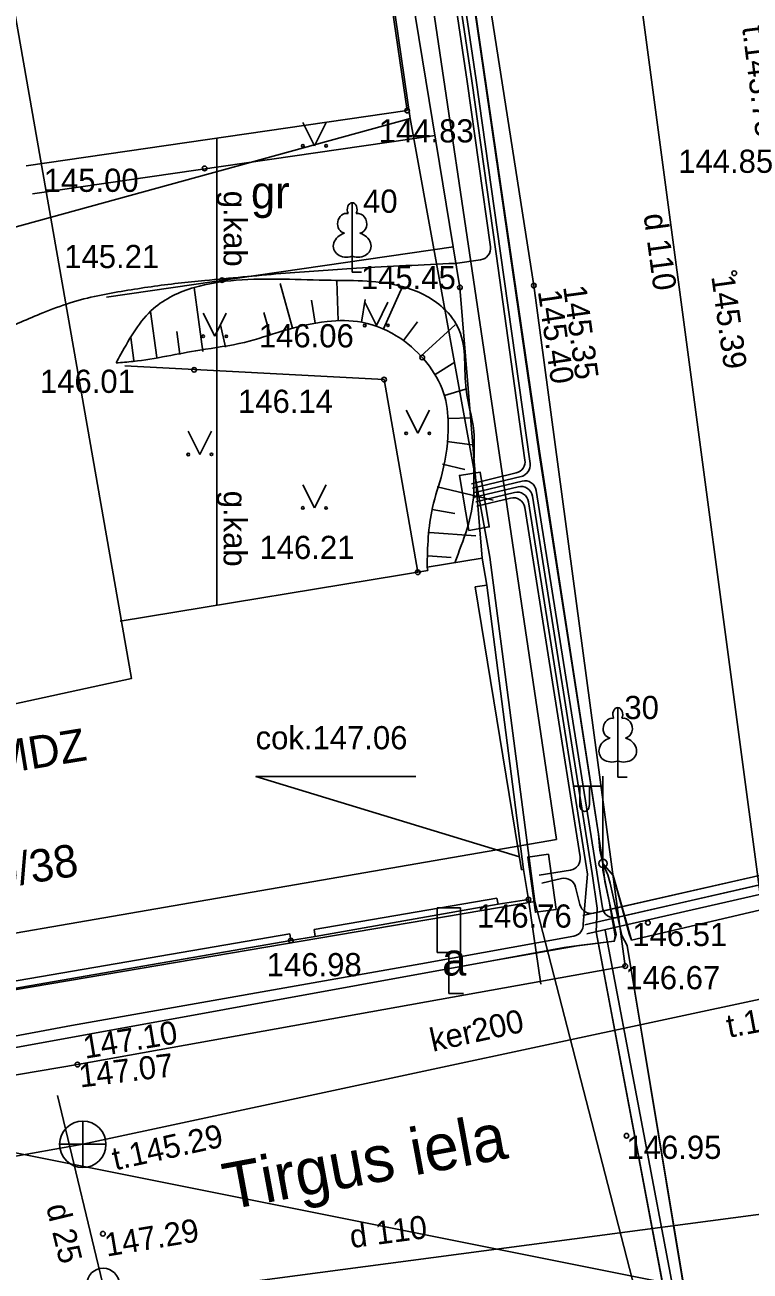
# Model space of a CAD drawing. Extents: x 728710 to 728960, y 272811 to 273475.
# Drawn here: x 728821.98 to 728837.6, y 272956.75 to 272983.61 of the extents above; entities that cross this region are included whole.
import ezdxf

# ---------------------------------------------------------------- set-up
doc = ezdxf.new("R2010")
doc.units = 0
for name, color, linetype in [('GEOD_ELEM_####_TKST_#', 7, 'Continuous'), ('Level 12', 7, 'Continuous'), ('Level 15', 7, 'Continuous'), ('Level 17', 7, 'Continuous'), ('Level 23', 7, 'Continuous'), ('Level 26', 7, 'Continuous'), ('Level 28', 7, 'Continuous'), ('Level 29', 7, 'Continuous'), ('Level 3', 7, 'Continuous'), ('Level 34', 7, 'Continuous'), ('Level 36', 7, 'Continuous'), ('Level 39', 7, 'Continuous'), ('Level 4', 7, 'Continuous'), ('Level 48', 7, 'Continuous'), ('Level 49', 7, 'Continuous'), ('Level 50', 7, 'Continuous'), ('Level 54', 7, 'Continuous'), ('Level 55', 7, 'Continuous'), ('Level 56', 7, 'Continuous'), ('Level 57', 7, 'Continuous'), ('Level 58', 7, 'Continuous'), ('Level 59', 7, 'Continuous'), ('Level 60', 7, 'Continuous'), ('Level 62', 7, 'Continuous'), ('Level 9', 7, 'Continuous'), ('RAMI_UZMR_####_####_#', 7, 'Continuous'), ('RELJ_ELEM_####_####_#', 7, 'Continuous'), ('RELJ_NOGA_####_####_#', 7, 'Continuous'), ('ROBZ_ELEM_####_####_#', 7, 'Continuous'), ('ROBZ_UZMR_####_####_#', 7, 'Continuous'), ('SAKT_VADV_PKAB_TKST_#', 7, 'Continuous'), ('TERT_ELEM_####_####_#', 7, 'Continuous'), ('TERT_KONT_####_####_#', 7, 'Continuous')]:
    doc.layers.add(name, color=color, linetype=linetype)

msp = doc.modelspace()

# ---------------------------------------------------------------- linework, layer by layer
at = {"layer": 'GEOD_ELEM_####_TKST_#'}
for points in [[(728834.432, 272965.54), (728834.353, 272966.059), (728834.337, 272966.173), (728833.056, 272974.371), (728829.783, 272996.939), (728828.856, 273003.445)], [(728834.651, 272965.281), (728835.049, 272963.886), (728848.214, 272966.974), (728858.246, 272968.805), (728863.75, 272969.856)], [(728811.293, 272959.669), (728811.951, 272959.783), (728832.038, 272963.44), (728833.873, 272963.761), (728834.677, 272963.862), (728834.716, 272964.011), (728834.498, 272965.033), (728834.427, 272965.397), (728834.432, 272965.54)], [(728834.957, 272963.773), (728836.299, 272955.654), (728837.635, 272946.696), (728838.556, 272941.827), (728839.286, 272937.451), (728841.341, 272924.237), (728842.91, 272914.786), (728843.079, 272914.144), (728843.387, 272914.165)]]:
    msp.add_lwpolyline(points, dxfattribs=at)
at = {"layer": 'Level 12'}
for p, q in [((728825.811, 272976.575), (728825.628, 272977.952)), ((728827.746, 272977.073), (728827.481, 272978.037)), ((728828.73, 272977.236), (728828.697, 272978.095)), ((728829.706, 272977.058), (728830.11, 272977.973)), ((728828.234, 272977.182), (728828.15, 272977.675)), ((728829.228, 272977.202), (728829.306, 272977.696)), ((728824.82, 272976.443), (728824.688, 272977.434)), ((728827.266, 272976.934), (728827.123, 272977.414)), ((728826.304, 272976.663), (728826.193, 272977.15)), ((728830.137, 272976.806), (728830.435, 272977.208)), ((728830.509, 272976.474), (728831.247, 272977.148)), ((728824.325, 272976.377), (728824.258, 272976.872)), ((728825.316, 272976.509), (728825.25, 272977.005)), ((728830.814, 272976.078), (728831.238, 272976.343)), ((728831.016, 272975.623), (728831.474, 272975.759)), ((728831.096, 272975.131), (728831.596, 272975.14)), ((728831.067, 272974.632), (728831.612, 272974.563)), ((728830.972, 272974.141), (728831.459, 272974.026)), ((728830.857, 272973.655), (728832.066, 272973.367)), ((728830.752, 272973.166), (728831.244, 272973.078)), ((728830.698, 272972.669), (728831.695, 272972.597)), ((728830.661, 272972.171), (728831.16, 272972.134))]:
    msp.add_line(p, q, dxfattribs=at)
msp.add_spline([(728830.643, 272971.921), (728830.76, 272973.208), (728830.969, 272973.952), (728831.096, 272974.994), (728830.999, 272975.681), (728830.636, 272976.329), (728830.076, 272976.85), (728829.238, 272977.201), (728828.491, 272977.219), (728827.534, 272977.015), (728826.707, 272976.768), (728825.748, 272976.602), (728824.313, 272976.359), (728823.942, 272976.326)], degree=3, dxfattribs=at)
at = {"layer": 'Level 15'}
for points in [[(728831.539, 272972.717), (728831.341, 272973.901), (728831.785, 272973.975), (728831.983, 272972.791)], [(728833.259, 272965.738), (728833.423, 272964.549), (728832.977, 272964.488), (728832.813, 272965.677)]]:
    msp.add_lwpolyline(points, close=True, dxfattribs=at)
at = {"layer": 'Level 17'}
for p, q in [((728822.683, 272960.538), (728823.746, 272956.12)), ((728823.317, 272956.063), (728838.727, 272958.097))]:
    msp.add_line(p, q, dxfattribs=at)
msp.add_lwpolyline([(728832.551, 273004.399), (728838.736, 272957.979), (728838.743, 272957.939)], dxfattribs=at)
at = {"layer": 'Level 23'}
for points in [[(728858.12, 272966.472), (728840.671, 272963.226), (728823.226, 272959.486)], [(728811.406, 272957.38), (728823.226, 272959.486)]]:
    msp.add_lwpolyline(points, dxfattribs=at)
at = {"layer": 'Level 26'}
for p, q in [((728834.432, 272965.54), (728834.432, 272967.423)), ((728834.432, 272967.207), (728833.797, 272967.202)), ((728833.932, 272967.203), (728833.932, 272966.811)), ((728834.142, 272967.205), (728834.142, 272966.811))]:
    msp.add_line(p, q, dxfattribs=at)
msp.add_circle((728834.432, 272965.54), 0.09, dxfattribs=at)
msp.add_ellipse((728834.037, 272966.811), major_axis=(0, 0.151), ratio=0.695971, start_param=1.570796, end_param=4.712389, dxfattribs=at)
at = {"layer": 'Level 28'}
msp.add_lwpolyline([(728824.13, 272976.264), (728829.716, 272975.966), (728830.442, 272971.814)], dxfattribs=at)
at = {"layer": 'Level 29'}
for p, q in [((728823.226, 272958.986), (728823.226, 272959.986)), ((728822.726, 272959.486), (728823.726, 272959.486))]:
    msp.add_line(p, q, dxfattribs=at)
msp.add_circle((728823.226, 272959.486), 0.5, dxfattribs=at)
at = {"layer": 'Level 3'}
for p, q in [((728830.214, 272981.763), (728828.214, 272995.554)), ((728822.008, 272980.573), (728830.214, 272981.763)), ((728831.832, 272972.116), (728830.645, 272971.922)), ((728830.657, 272971.849), (728830.645, 272971.922)), ((728831.832, 272972.116), (728831.927, 272971.539)), ((728830.657, 272971.849), (728824.031, 272970.764)), ((728831.927, 272971.539), (728831.679, 272971.498)), ((728831.679, 272971.498), (728832.677, 272965.404)), ((728832.677, 272965.404), (728832.722, 272965.412)), ((728832.828, 272964.761), (728832.722, 272965.412)), ((728832.148, 272964.79), (728828.208, 272964.113)), ((728832.148, 272964.79), (728832.171, 272964.659)), ((728832.171, 272964.659), (728832.828, 272964.761)), ((728827.684, 272964.024), (728820.383, 272962.77)), ((728827.684, 272964.024), (728827.709, 272963.879)), ((728827.709, 272963.879), (728828.233, 272963.965)), ((728828.233, 272963.965), (728828.208, 272964.113))]:
    msp.add_line(p, q, dxfattribs=at)
at = {"layer": 'Level 34'}
msp.add_spline([(728831.238, 272972.019), (728831.647, 272973.514), (728831.647, 272974), (728831.647, 272974.864), (728831.483, 272975.754), (728831.337, 272977.03), (728830.991, 272977.509), (728830.11, 272977.973), (728828.574, 272978.107), (728826.529, 272978.107), (728825.628, 272977.952), (728824.749, 272977.496), (728824.046, 272976.512), (728823.942, 272976.326)], degree=3, dxfattribs=at)
at = {"layer": 'Level 36'}
for p, q in [((728843.89, 272966.667), (728833.996, 272964.414)), ((728843.934, 272966.472), (728834.04, 272964.219)), ((728843.978, 272966.277), (728834.084, 272964.024)), ((728835.963, 272955.182), (728834.286, 272964.063)), ((728836.159, 272955.22), (728834.483, 272964.1))]:
    msp.add_line(p, q, dxfattribs=at)
at = {"layer": 'Level 39'}
msp.add_circle((728823.663, 272956.465), 0.351, dxfattribs=at)
at = {"layer": 'Level 4'}
for p, q in [((728828.085, 272997.852), (728831.352, 272977.953)), ((728822.145, 272979.97), (728830.814, 272981.227)), ((728823.737, 272977.743), (728831.209, 272978.826)), ((728831.927, 272971.539), (728832.722, 272965.412)), ((728828.233, 272963.965), (728832.171, 272964.659)), ((728820.41, 272962.613), (728827.709, 272963.879))]:
    msp.add_line(p, q, dxfattribs=at)
for points in [[(728791.727, 273091.506), (728811.654, 273095.023), (728814.654, 273095.178), (728815.22, 273095.032), (728815.785, 273094.657), (728816.384, 273093.154), (728816.384, 273093.154), (728817.477, 273084.163), (728819.263, 273073.354), (728821.261, 273057.957), (728825.757, 273025.679), (728827.763, 273011.141), (728832.943, 272977.993), (728834.913, 272963.328)], [(728831.352, 272977.953), (728831.352, 272977.953), (728831.832, 272972.116)], [(728832.828, 272964.761), (728833.093, 272962.938)], [(728811.329, 272959.211), (728823.111, 272961.205), (728834.913, 272963.328)]]:
    msp.add_lwpolyline(points, dxfattribs=at)
at = {"layer": 'Level 48'}
for centre in [(728830.214, 272981.763), (728825.85, 272980.518), (728826.226, 272978.109), (728837.26, 272978.259), (728831.352, 272977.953), (728832.943, 272977.993), (728830.538, 272976.443), (728825.624, 272976.177), (728829.716, 272975.966), (728830.442, 272971.814), (728832.828, 272964.761), (728832.828, 272964.761), (728835.402, 272964.259), (728827.709, 272963.879), (728834.913, 272963.328), (728823.111, 272961.205), (728834.939, 272959.672), (728823.659, 272957.558)]:
    msp.add_circle(centre, 0.05, dxfattribs=at)
at = {"layer": 'Level 49'}
for p, q in [((728831.36, 272964.586), (728830.86, 272964.586)), ((728830.86, 272963.617), (728830.86, 272964.586)), ((728831.36, 272963.617), (728831.36, 272964.586)), ((728831.36, 272963.617), (728830.86, 272963.617)), ((728831.114, 272963.617), (728831.114, 272962.739)), ((728831.114, 272962.739), (728831.429, 272962.739))]:
    msp.add_line(p, q, dxfattribs=at)
at = {"layer": 'Level 9'}
msp.add_lwpolyline([(728832.632, 272965.68), (728826.956, 272967.411), (728830.401, 272967.411)], dxfattribs=at)
at = {"layer": 'RAMI_UZMR_####_####_#'}
for points in [[(728810.894, 273070.336), (728816.634, 273032.011), (728817.26, 273023.998), (728805.412, 273016.121), (728806.079, 273011.62), (728806.601, 273008.097), (728806.659, 273004.632), (728817.58, 273007.699), (728824.279, 272969.525), (728810.963, 272966.628), (728810.935, 272966.213), (728811.098, 272962.191), (728811.981, 272950.771), (728813.612, 272944.45), (728830.483, 272947.485), (728837.542, 272895.947)], [(728826.111, 272981.168), (728826.111, 272971.105)], [(728846.661, 272954.322), (728808.413, 272961.978)]]:
    msp.add_lwpolyline(points, dxfattribs=at)
at = {"layer": 'RELJ_ELEM_####_####_#'}
for points in [[(728828.856, 273003.445), (728828.857, 273003.328), (728828.884, 273003.229), (728829.195, 273001.031), (728829.783, 272996.939), (728833.068, 272974.423), (728834.337, 272966.173), (728834.366, 272965.827), (728834.432, 272965.54)], [(728834.432, 272965.54), (728834.651, 272965.281), (728835, 272964.019), (728835.049, 272963.886), (728848.214, 272966.974), (728858.392, 272968.826), (728863.751, 272969.849)], [(728834.432, 272965.54), (728834.469, 272965.147), (728834.567, 272964.725), (728834.647, 272964.268), (728834.693, 272963.982), (728834.677, 272963.862), (728833.915, 272963.774), (728833.593, 272963.726), (728832.038, 272963.44), (728811.951, 272959.783), (728811.293, 272959.669)], [(728834.432, 272965.54), (728834.536, 272965.293), (728834.587, 272965.117), (728834.841, 272963.989), (728834.957, 272963.773), (728836.308, 272955.611), (728837.635, 272946.696), (728838.556, 272941.827), (728839.268, 272937.476), (728841.341, 272924.237), (728842.866, 272915.111), (728843.079, 272914.144), (728843.48, 272914.19), (728843.48, 272914.19)]]:
    msp.add_lwpolyline(points, dxfattribs=at)
at = {"layer": 'ROBZ_ELEM_####_####_#'}
for points in [[(728815.186, 273091.969), (728820.435, 273053.684), (728833.431, 272966.054)], [(728833.431, 272966.054), (728811.098, 272962.191)]]:
    msp.add_lwpolyline(points, dxfattribs=at)
at = {"layer": 'ROBZ_UZMR_####_####_#'}
for p, q in [((728830.282, 272981.594), (728827.162, 273002.983)), ((728810.211, 272976.079), (728830.282, 272981.594)), ((728831.997, 272972.139), (728830.282, 272981.594)), ((728832.964, 272964.716), (728831.997, 272972.139)), ((728815.289, 272961.715), (728832.964, 272964.716)), ((728832.964, 272964.716), (728835.497, 272954.911))]:
    msp.add_line(p, q, dxfattribs=at)
at = {"layer": 'TERT_ELEM_####_####_#'}
for p, q in [((728831.794, 272978.548), (728831.245, 272978.471)), ((728831.597, 272973.723), (728832.562, 272973.956)), ((728832.673, 272973.88), (728831.621, 272973.626)), ((728832.688, 272973.78), (728831.644, 272973.529)), ((728831.668, 272973.431), (728832.606, 272973.658)), ((728832.525, 272973.535), (728831.691, 272973.334)), ((728834.42, 272964.579), (728832.994, 272973.577)), ((728832.443, 272973.413), (728831.715, 272973.237)), ((728834.102, 272965.309), (728832.83, 272973.331)), ((728832.912, 272973.454), (728834.2, 272965.325)), ((728833.941, 272965.682), (728832.748, 272973.209))]:
    msp.add_line(p, q, dxfattribs=at)
for points in [[(728828.26, 273004.941), (728829.532, 272996.848), (728830.273, 272992.035), (728831.703, 272982.416), (728832.228, 272978.691), (728832.862, 272974.157)], [(728829.386, 272996.48), (728830.075, 272992.005), (728831.505, 272982.388), (728832.006, 272978.83)], [(728832.751, 272974.233), (728832.129, 272978.677), (728831.604, 272982.402), (728830.174, 272992.02), (728829.47, 272996.592)], [(728843.673, 272966.618), (728834.234, 272964.468)], [(728843.934, 272966.472), (728834.722, 272964.374)], [(728833.058, 272965.289), (728833.734, 272965.396)], [(728833.542, 272965.212), (728833.118, 272965.113)], [(728834.009, 272964.232), (728834.102, 272965.309)], [(728834.2, 272965.325), (728834.309, 272964.578)], [(728833.936, 272964.651), (728833.842, 272965.029)], [(728834.309, 272964.578), (728834.286, 272964.063), (728835.963, 272955.182)], [(728811.277, 272959.875), (728816.573, 272960.847), (728822.985, 272962.05), (728830.511, 272963.377), (728833.804, 272963.973)]]:
    msp.add_lwpolyline(points, dxfattribs=at)
for centre, start, end in [((728831.759, 272978.795), 277.9646, 8.0224), ((728832.503, 272974.199), 283.5618, 7.9646), ((728832.615, 272974.123), 283.5618, 7.9646), ((728832.583, 272973.292), 9.0063, 103.5618), ((728832.665, 272973.415), 9.0063, 103.5618), ((728832.747, 272973.537), 9.0063, 103.5618), ((728832.501, 272973.17), 9.0063, 103.5618), ((728833.694, 272965.643), 279.0063, 9.0063), ((728833.599, 272964.969), 14.0423, 103.1395), ((728834.179, 272964.712), 194.0423, 282.8283), ((728834.667, 272964.618), 189.0063, 282.8283), ((728833.759, 272964.219), 280.2665, 2.9995)]:
    msp.add_arc(centre, 0.25, start, end, dxfattribs=at)
msp.add_spline([(728831.245, 272978.471), (728829.122, 272978.366), (728827.489, 272978.251), (728826.673, 272978.178), (728825.857, 272978.103), (728825.278, 272978.043), (728824.701, 272977.969), (728824.126, 272977.879), (728823.552, 272977.774), (728822.951, 272977.619), (728822.367, 272977.405), (728821.422, 272976.994), (728820.495, 272976.548), (728817.073, 272974.736), (728814.062, 272972.937), (728811.171, 272970.703), (728810.481, 272970.168)], degree=3, dxfattribs=at)
at = {"layer": 'TERT_KONT_####_####_#'}
for p, q in [((728827.968, 272981.504), (728828.218, 272981.004)), ((728828.218, 272981.004), (728828.468, 272981.504)), ((728829.03, 272978.626), (728829.03, 272978.279)), ((728829.03, 272978.279), (728829.23, 272978.279)), ((728829.301, 272977.635), (728829.551, 272977.135)), ((728829.551, 272977.135), (728829.801, 272977.635)), ((728825.818, 272977.4), (728826.068, 272976.9)), ((728826.068, 272976.9), (728826.318, 272977.4)), ((728830.194, 272975.31), (728830.444, 272974.81)), ((728830.444, 272974.81), (728830.694, 272975.31)), ((728825.499, 272974.855), (728825.749, 272974.355)), ((728825.749, 272974.355), (728825.999, 272974.855)), ((728827.968, 272973.7), (728828.218, 272973.2)), ((728828.218, 272973.2), (728828.468, 272973.7)), ((728834.751, 272967.746), (728834.751, 272967.399)), ((728834.751, 272967.399), (728834.951, 272967.399))]:
    msp.add_line(p, q, dxfattribs=at)
for points in [[(728829.03, 272979.779), (728829.03, 272978.626)], [(728829.119, 272979.546), (728829.118, 272979.547)], [(728834.751, 272968.899), (728834.751, 272967.746)], [(728834.841, 272968.667), (728834.84, 272968.668)]]:
    msp.add_lwpolyline(points, dxfattribs=at)
for centre, radius in [((728827.968, 272981.004), 0.028), ((728828.468, 272981.004), 0.0263), ((728829.3, 272977.134), 0.028), ((728829.8, 272977.134), 0.0263), ((728825.818, 272976.9), 0.028), ((728826.318, 272976.9), 0.0263), ((728830.194, 272974.809), 0.028), ((728830.694, 272974.809), 0.0263), ((728825.499, 272974.354), 0.028), ((728825.999, 272974.354), 0.0263), ((728827.968, 272973.2), 0.028), ((728828.468, 272973.2), 0.0263)]:
    msp.add_circle(centre, radius, dxfattribs=at)
for centre, major_axis, ratio, start_param, end_param in [((728829.03, 272979.629), (0, -0.15), 0.707107, 3.14537, 5.287485), ((728829.029, 272979.629), (0, -0.15), 0.707107, 0.995701, 3.137816), ((728828.902, 272979.334), (-0.039, -0.212), 0.861323, 3.141593, 6.283185), ((728829.158, 272979.334), (0.039, -0.212), 0.861323, 0, 3.141593), ((728828.94, 272978.872), (0.307, 0.095), 0.814445, 1.570796, 4.752015), ((728829.119, 272978.872), (-0.307, 0.095), 0.814445, 1.531171, 4.712389), ((728834.751, 272968.749), (0, -0.15), 0.707107, 3.14537, 5.287485), ((728834.751, 272968.749), (0, -0.15), 0.707107, 0.995701, 3.137816), ((728834.623, 272968.454), (-0.039, -0.212), 0.861323, 3.141593, 6.283185), ((728834.879, 272968.454), (0.039, -0.212), 0.861323, 0, 3.141593), ((728834.661, 272967.992), (0.307, 0.095), 0.814445, 1.570796, 4.752015), ((728834.841, 272967.992), (-0.307, 0.095), 0.814445, 1.531171, 4.712389)]:
    msp.add_ellipse(centre, major_axis=major_axis, ratio=ratio, start_param=start_param, end_param=end_param, dxfattribs=at)

# ---------------------------------------------------------------- texts
at = {"layer": 'Level 50'}
msp.add_text('cok.147.06', height=0.5, dxfattribs=at).set_placement((728826.949, 272967.999))
at = {"layer": 'Level 54'}
msp.add_text('Tirgus iela', height=1, rotation=10.472, dxfattribs=at).set_placement((728826.352, 272958.071))
at = {"layer": 'Level 55'}
for s, rotation, p in [('d 110', 277.5889, (728835.306, 272979.518)), ('d 25', 283.5287, (728822.434, 272958.145)), ('d 110', 7.5172, (728829.01, 272957.248))]:
    msp.add_text(s, height=0.5, rotation=rotation, dxfattribs=at).set_placement(p)
at = {"layer": 'Level 56'}
msp.add_text(' 144.85', height=0.5, dxfattribs=at).set_placement((728835.868, 272980.422))
at = {"layer": 'Level 57'}
for s, p in [(' 144.83', (728829.416, 272981.077)), (' 145.00', (728822.199, 272980.012)), (' 145.21', (728822.641, 272978.369)), ('145.45', (728829.217, 272977.916)), (' 146.06', (728826.833, 272976.661)), (' 146.01', (728822.117, 272975.68)), (' 146.14', (728826.385, 272975.249)), (' 146.21', (728826.847, 272972.1)), (' 146.76', (728831.529, 272964.156)), (' 146.51', (728834.878, 272963.759)), (' 146.98', (728827.003, 272963.108)), ('146.67', (728834.913, 272962.828)), ('146.95', (728834.939, 272959.172))]:
    msp.add_text(s, height=0.5, dxfattribs=at).set_placement(p)
for s, rotation, p in [('145.39', 277.866, (728836.765, 272978.191)), ('145.40', 278.229, (728833.028, 272977.87)), ('145.35', 277.7729, (728833.573, 272977.969)), ('147.10', 9.4698, (728823.277, 272961.329)), ('147.07', 6.9286, (728823.171, 272960.709)), ('147.29', 9.4403, (728823.741, 272957.065))]:
    msp.add_text(s, height=0.5, rotation=rotation, dxfattribs=at).set_placement(p)
at = {"layer": 'Level 58'}
for s, p in [('gr', (728826.849, 272979.654)), ('a', (728830.968, 272963.123))]:
    msp.add_text(s, height=0.7, dxfattribs=at).set_placement(p)
at = {"layer": 'Level 59'}
msp.add_text('MDZ', height=0.7, rotation=9.298, dxfattribs=at).set_placement((728821.342, 272967.441))
at = {"layer": 'Level 60'}
for s, rotation, p in [('t.143.75', 277.195, (728837.428, 272983.564)), ('t.145.06', 10.538, (728837.143, 272961.78)), ('ker200', 12.391, (728830.765, 272961.479)), ('t.145.29', 12.391, (728823.922, 272958.923))]:
    msp.add_text(s, height=0.5, rotation=rotation, dxfattribs=at).set_placement(p)
at = {"layer": 'Level 62'}
msp.add_text('10/38', height=0.7, rotation=9.298, dxfattribs=at).set_placement((728820.852, 272964.903))
at = {"layer": 'RELJ_NOGA_####_####_#'}
for s, p in [('40', (728829.265, 272979.561)), ('30', (728834.893, 272968.65))]:
    msp.add_text(s, height=0.5, dxfattribs=at).set_placement(p)
at = {"layer": 'SAKT_VADV_PKAB_TKST_#'}
for p in [(728826.261, 272980.036), (728826.261, 272973.571)]:
    msp.add_text('g.kab', height=0.5, rotation=270, dxfattribs=at).set_placement(p)

doc.saveas('drawing.dxf')
